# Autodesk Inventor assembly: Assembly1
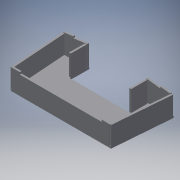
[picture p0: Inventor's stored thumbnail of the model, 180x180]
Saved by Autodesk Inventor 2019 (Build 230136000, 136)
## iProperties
Created: 2019-01
Part Number: Assembly1
Document SubType Name: Assembly
Designer: Guy Link
Author: Guy Link
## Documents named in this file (6)
- G:\Parts_Library\Assembly1.iam
- G:\Parts_Library\17.ipt
- G:\Parts_Library\18.ipt
- G:\Parts_Library\21.ipt
- G:\Parts_Library\19.ipt
- C:\Users\Guy Link\Desktop\20.ipt
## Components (8 placed, 5 different names)
1. 17:1 — Mate:1, Mate:2, Flush:1, Mate:3, Flush:2, Mate:4, Mate:5, Mate:6, Flush:3, Mate:7, Mate:8, Flush:4, Flush:5, Mate:9, Mate:10, Flush:6, Flush:7
2. 18:1 — Mate:2, Flush:1
3. 21:1 — Mate:8, Flush:5
4. 21:2 — Mate:7, Flush:4
5. 19:1 — Mate:3, Flush:2
6. 19:2 — Mate:6, Flush:3
7. 20:1 — Mate:9, Flush:6
8. 20:2 — Mate:10, Flush:7
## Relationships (17: Mate 10, Flush 7)
- Mate:1: 17:1
- Mate:2: 17:1 ↔ 18:1
- Flush:1: 17:1 ↔ 18:1
- Mate:3: 17:1 ↔ 19:1
- Flush:2: 17:1 ↔ 19:1
- Mate:4: 17:1
- Mate:5: 17:1
- Mate:6: 17:1 ↔ 19:2
- Flush:3: 17:1 ↔ 19:2
- Mate:7: 17:1 ↔ 21:2
- Mate:8: 17:1 ↔ 21:1
- Flush:4: 17:1 ↔ 21:2
- Flush:5: 17:1 ↔ 21:1
- Mate:9: 17:1 ↔ 20:1
- Mate:10: 17:1 ↔ 20:2
- Flush:6: 17:1 ↔ 20:1
- Flush:7: 17:1 ↔ 20:2
